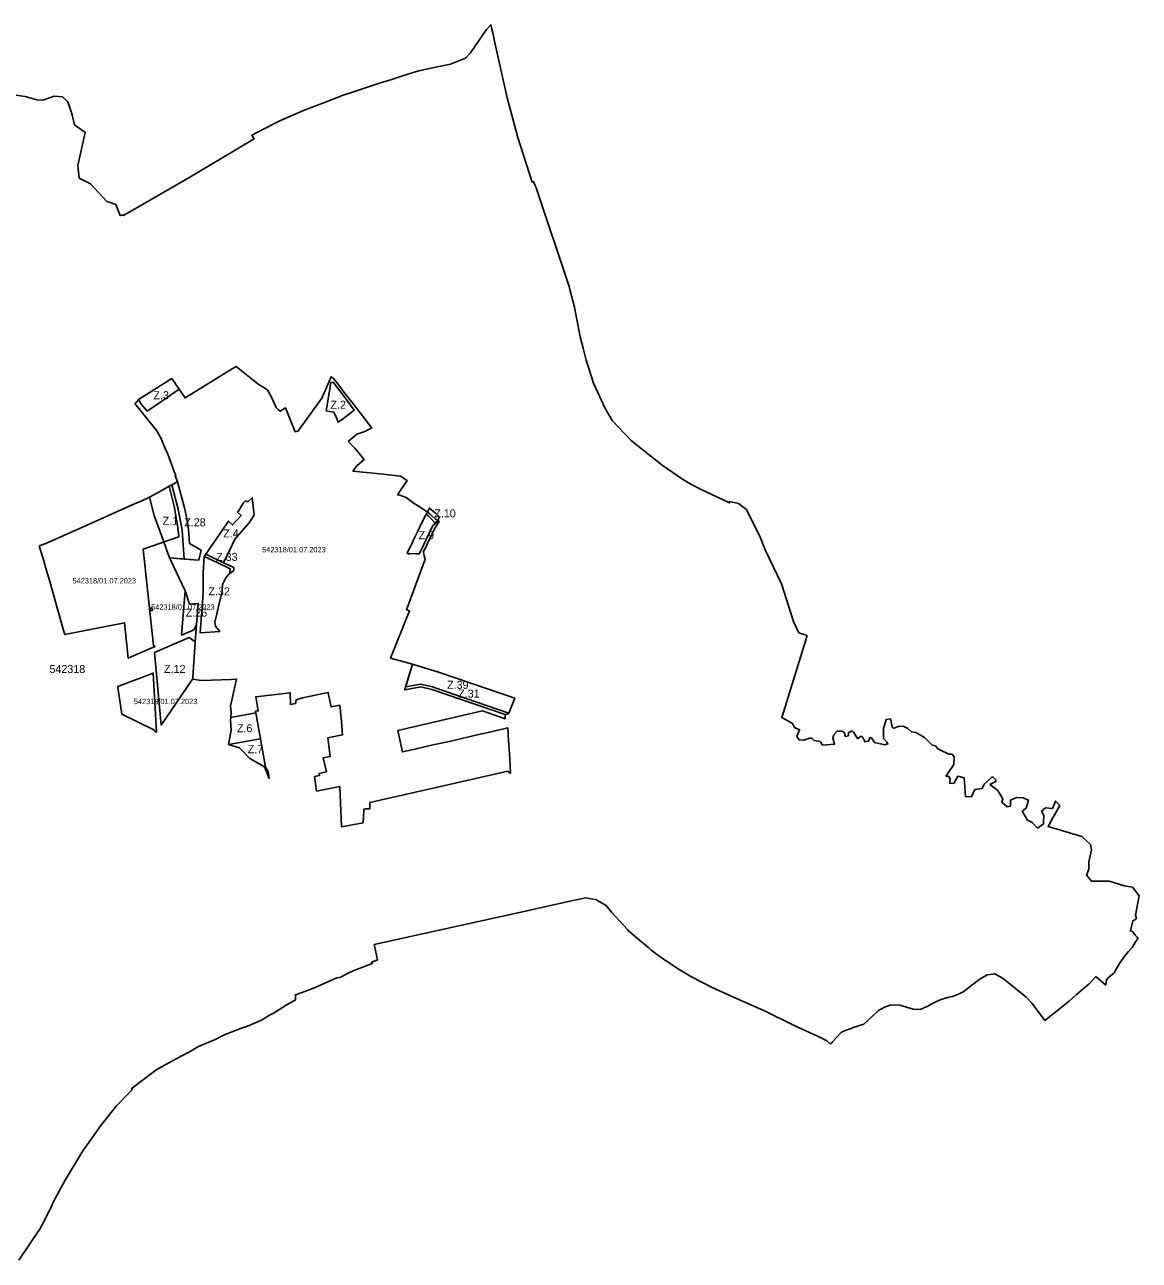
# Model space of a CAD drawing. Extents: x -522079 to -518833, y -1142400 to -1139961.
# Drawn here: x -520921 to -518833, y -1142277 to -1139961 of the extents above; entities that cross this region are included whole.
import ezdxf

# ---------------------------------------------------------------- set-up
doc = ezdxf.new("R2010")
doc.units = 0
for name, color, linetype in [('95410013', 7, 'Continuous'), ('95420023', 7, 'Continuous'), ('95440013', 7, 'Continuous')]:
    doc.layers.add(name, color=color, linetype=linetype)

msp = doc.modelspace()

# ---------------------------------------------------------------- linework, layer by layer
at = {"layer": '95410013'}
for points in [[(-520715.02, -1140671.04), (-520699.13, -1140690.61), (-520673.31, -1140722.41), (-520669.12, -1140730.36), (-520666.3, -1140735.71), (-520657.82, -1140755.57), (-520652.69, -1140766.32), (-520641.11, -1140798.37), (-520638.22, -1140805.93), (-520639.14, -1140806.35), (-520634.79, -1140817.77), (-520621.9, -1140866.86), (-520618.56, -1140880.81), (-520614.37, -1140907.34), (-520612.5, -1140933.48), (-520590.36, -1140946.34), (-520594.75, -1140964.79), (-520649.51, -1140960.76), (-520648.03, -1140963.9), (-520620.51, -1141022.34), (-520612.04, -1141047.58), (-520596.21, -1141046.3), (-520599.33, -1141085.41), (-520601.54, -1141117.64), (-520606.07, -1141183.78), (-520607.02, -1141187.64), (-520589.77, -1141190.43), (-520534.17, -1141188.18), (-520524.27, -1141187.6), (-520535.7, -1141238.47), (-520534.05, -1141249.88), (-520534.84, -1141259.42), (-520488.31, -1141251.1), (-520488.89, -1141247.94), (-520483.58, -1141247.19), (-520488.14, -1141220.84), (-520423.9, -1141213.13), (-520423.33, -1141235.38), (-520413.51, -1141233.43), (-520412.54, -1141226.76), (-520400.61, -1141222.82), (-520352.79, -1141212.63), (-520352.51, -1141213.97), (-520352.46, -1141213.96), (-520347.19, -1141239.81), (-520330.62, -1141236.74), (-520328.39, -1141261.02), (-520327.05, -1141275.53), (-520325.5, -1141292.44), (-520353.1, -1141297.63), (-520348.74, -1141332.58), (-520362.13, -1141335.31), (-520355.94, -1141361.7), (-520369.53, -1141364.42), (-520368.84, -1141368.35), (-520378.01, -1141370.07), (-520374.09, -1141397.41), (-520330.86, -1141389.2), (-520329.77, -1141404.14), (-520327.5, -1141464.71), (-520287.25, -1141456.97), (-520285.53, -1141433.12), (-520285.62, -1141431.18), (-520283.46, -1141431.12), (-520277.92, -1141430.99), (-520274.48, -1141431.01), (-520274.28, -1141419.2), (-520155.8, -1141392.1), (-520016.19, -1141360.33), (-520010.91, -1141364.55), (-520011.78, -1141349.43), (-520013.01, -1141327.96), (-520014.41, -1141303.65), (-520015.8, -1141279.3), (-520055.42, -1141288.36), (-520062.28, -1141289.92), (-520088.69, -1141295.96), (-520120.09, -1141303.14), (-520128.28, -1141304.98), (-520135.15, -1141306.52), (-520161.5, -1141312.42), (-520200.99, -1141321.26), (-520207.86, -1141322.8), (-520213.54, -1141324.07), (-520221.2, -1141287.03), (-520221.83, -1141283.92), (-520063.43, -1141247.22), (-520020.82, -1141261.97), (-520020.92, -1141254.2), (-520158.56, -1141206.98), (-520178.85, -1141202.22), (-520209, -1141207.86), (-520194.38, -1141159.65), (-520235.62, -1141148.58), (-520200.4, -1141059.73), (-520205.51, -1141057.7), (-520170.88, -1140963.13), (-520172.97, -1140956.99), (-520173.77, -1140949.3), (-520154.18, -1140907.23), (-520146.75, -1140896.12), (-520145.76, -1140894.15), (-520144.78, -1140892.2), (-520147.23, -1140890.72), (-520151.38, -1140888.23), (-520158.87, -1140881.01), (-520161.92, -1140878.07), (-520166.62, -1140874.78), (-520176.48, -1140867.88), (-520180.27, -1140865.22), (-520191.59, -1140858.73), (-520196.46, -1140855.08), (-520206.43, -1140847.59), (-520220.12, -1140842.45), (-520222.55, -1140842.43), (-520204.62, -1140815.75), (-520216.9, -1140807.42), (-520249.32, -1140803.75), (-520306.3, -1140797.86), (-520298.77, -1140787.91), (-520285.25, -1140776.21), (-520302.54, -1140754.92), (-520303.74, -1140753.44), (-520314.83, -1140742.62), (-520298.98, -1140728.74), (-520284.03, -1140723.41), (-520276.72, -1140720.19), (-520270.86, -1140717.61), (-520287.89, -1140694.59), (-520300.9, -1140678.05), (-520307.57, -1140669.43), (-520324.2, -1140648.06), (-520334.5, -1140634.63), (-520342.44, -1140624.55), (-520346.89, -1140621.24), (-520364.42, -1140661.36), (-520399.89, -1140710.42), (-520399.9, -1140710.42), (-520405.96, -1140718.81), (-520407.37, -1140721.08), (-520408.23, -1140722.45), (-520414.39, -1140724.32), (-520422.23, -1140704.1), (-520432.59, -1140679.54), (-520442.27, -1140685.74), (-520445.91, -1140682.53), (-520449.96, -1140678.96), (-520457.96, -1140660.67), (-520465.4, -1140646.75), (-520470.21, -1140643.01), (-520481.74, -1140636.06), (-520493.55, -1140626.8), (-520525.02, -1140602.15), (-520527.15, -1140603.46), (-520617.05, -1140658.61), (-520620.66, -1140660.83), (-520631.48, -1140644.23), (-520662.52, -1140665.44), (-520691.74, -1140685.4), (-520702.26, -1140672.84), (-520707.94, -1140663.79), (-520710.41, -1140667.24)], [(-520893.74, -1140937.98), (-520888.93, -1140954.41), (-520885.58, -1140965.84), (-520881.52, -1140979.72), (-520872.93, -1141009.05), (-520861.45, -1141049.84), (-520847.24, -1141100.33), (-520846.14, -1141104.23), (-520733.88, -1141082.24), (-520727.16, -1141148.38), (-520686.99, -1141131.09), (-520676.95, -1141126.77), (-520679.92, -1141124.76), (-520682.4, -1141101.39), (-520695.94, -1140973.65), (-520699.09, -1140943.92), (-520632.04, -1140920.85), (-520634.37, -1140902.81), (-520641.23, -1140863.72), (-520646.19, -1140843.58), (-520650.7, -1140826.31), (-520665.74, -1140834.79), (-520687.49, -1140846.81), (-520701.37, -1140853.35), (-520715.12, -1140859.45), (-520801.45, -1140897.78), (-520881.74, -1140933.43)], [(-520681.75, -1141059.18), (-520682.32, -1141054.61), (-520685.9, -1141055.06), (-520685.33, -1141059.63)], [(-520674.18, -1141286.49), (-520680.34, -1141176.38), (-520746.65, -1141201.66), (-520746.38, -1141203.48), (-520739.03, -1141253.62), (-520679.28, -1141282.96), (-520675.31, -1141287.41)]]:
    msp.add_lwpolyline(points, close=True, dxfattribs=at)
at = {"layer": '95420023'}
for points in [[(-520631.48, -1140644.23), (-520645.69, -1140624.14), (-520707.94, -1140663.79), (-520702.26, -1140672.84), (-520691.74, -1140685.4), (-520662.52, -1140665.44)], [(-520351.39, -1140655.57), (-520356.53, -1140684.75), (-520353.6, -1140685.32), (-520345.87, -1140686.81), (-520341.7, -1140687.61), (-520339.66, -1140692.44), (-520335.84, -1140701.48), (-520334.3, -1140706.02), (-520326.31, -1140701.14), (-520303.56, -1140683.6), (-520324.4, -1140655.71), (-520343.28, -1140631.04), (-520347.36, -1140631.75)], [(-520687.49, -1140846.81), (-520678.48, -1140881.15), (-520660.47, -1140930.63), (-520649.51, -1140960.76), (-520622.44, -1140962.75), (-520626.29, -1140908.87), (-520633.62, -1140869.48), (-520645.66, -1140823.61), (-520650.7, -1140826.31), (-520665.74, -1140834.79)], [(-520622.44, -1140962.75), (-520594.75, -1140964.79), (-520590.36, -1140946.34), (-520612.5, -1140933.48), (-520614.37, -1140907.34), (-520618.56, -1140880.81), (-520621.9, -1140866.86), (-520634.79, -1140817.77), (-520645.66, -1140823.61), (-520633.62, -1140869.48), (-520626.29, -1140908.87)], [(-520197.39, -1140937.44), (-520204.29, -1140951.99), (-520201.3, -1140953.32), (-520201.27, -1140953.32), (-520200.79, -1140952.24), (-520189.01, -1140952.86), (-520181.77, -1140953.24), (-520180.26, -1140950.09), (-520156.19, -1140899.86), (-520151.68, -1140896.26), (-520164.55, -1140881.96), (-520168.95, -1140879.03), (-520170.08, -1140881.1), (-520178.74, -1140898.05), (-520184.7, -1140910.65), (-520191.17, -1140924.29), (-520193, -1140928.16), (-520196.08, -1140934.67)], [(-520168.95, -1140879.03), (-520164.55, -1140881.96), (-520151.68, -1140896.26), (-520149.94, -1140892.73), (-520148.74, -1140894), (-520148.27, -1140892.97), (-520147.23, -1140890.72), (-520143.83, -1140883.35), (-520152.09, -1140876.15), (-520162.5, -1140867.24), (-520166.62, -1140874.78), (-520167.79, -1140876.9)], [(-520536.52, -1140989.65), (-520536.41, -1140980.8), (-520560.76, -1140969.3), (-520584.75, -1140957.97), (-520586.68, -1140988.64), (-520586.76, -1141021.16), (-520586.99, -1141025.98), (-520587.85, -1141044.25), (-520588.29, -1141049.68), (-520590.32, -1141074.97), (-520592.43, -1141100.83), (-520555.74, -1141098.46), (-520563.4, -1141088.78), (-520565.18, -1141081.15), (-520561.24, -1141065.24), (-520556.5, -1141046.1), (-520551.07, -1141024.16), (-520550.66, -1141010.15), (-520545.15, -1140999.12), (-520540.36, -1140992.71)], [(-520596.21, -1141046.3), (-520612.04, -1141047.58), (-520620.51, -1141022.34), (-520627.13, -1141105.32), (-520605.48, -1141096), (-520603.47, -1141094.45), (-520599.33, -1141085.41)], [(-520601.54, -1141117.64), (-520612.8, -1141110.04), (-520677.78, -1141138.02), (-520665.65, -1141273.94), (-520607.02, -1141187.64), (-520606.07, -1141183.78)], [(-520194.38, -1141159.65), (-520207.36, -1141202.47), (-520178.73, -1141197.11), (-520176.64, -1141197.6), (-520157.17, -1141202.17), (-520156.44, -1141202.42), (-520153.86, -1141203.31), (-520013.82, -1141251.35), (-520002.99, -1141223.35), (-520143.75, -1141175.06)], [(-520209, -1141207.86), (-520178.85, -1141202.22), (-520158.56, -1141206.98), (-520020.92, -1141254.2), (-520014.17, -1141252.24), (-520013.82, -1141251.35), (-520153.86, -1141203.31), (-520156.44, -1141202.42), (-520157.17, -1141202.17), (-520176.64, -1141197.6), (-520178.73, -1141197.11), (-520207.36, -1141202.47)], [(-520488.31, -1141251.1), (-520534.84, -1141259.42), (-520535.3, -1141264.93), (-520534.35, -1141283.17), (-520539.2, -1141310.09), (-520479.49, -1141299.41)], [(-520479.49, -1141299.41), (-520539.2, -1141310.09), (-520518.61, -1141316.36), (-520499.06, -1141336.21), (-520471.76, -1141351.9), (-520463.1, -1141373.93), (-520465.21, -1141361), (-520469.72, -1141352.88)]]:
    msp.add_lwpolyline(points, close=True, dxfattribs=at)
for points in [[(-520514.41, -1140910.27), (-520500.98, -1140895.73), (-520497.04, -1140889.19), (-520491.41, -1140879.85), (-520492.53, -1140869.55), (-520494.89, -1140847.8), (-520502.85, -1140855.53), (-520507.49, -1140853.67), (-520511.48, -1140857.9), (-520516.84, -1140866.53), (-520521.46, -1140873.68)], [(-520515.64, -1140881.37), (-520531.52, -1140898.7), (-520538.57, -1140892.18), (-520539.31, -1140891.51), (-520549.95, -1140907.16), (-520562.58, -1140925.73), (-520581.88, -1140953.8), (-520548.43, -1140969.6), (-520536.98, -1140945.57), (-520527.38, -1140925.42), (-520514.41, -1140910.27)], [(-520521.46, -1140873.68), (-520522.62, -1140874.92)], [(-520522.62, -1140874.92), (-520515.64, -1140881.37)], [(-520581.88, -1140953.8), (-520584.75, -1140957.97), (-520560.76, -1140969.3), (-520536.41, -1140980.8), (-520536.52, -1140989.65), (-520529.52, -1140984.06), (-520529.45, -1140978.56), (-520536.34, -1140975.31), (-520548.43, -1140969.6), (-520581.88, -1140953.8)]]:
    msp.add_lwpolyline(points, dxfattribs=at)
at = {"layer": '95440013'}
msp.add_lwpolyline([(-520941.45, -1140093.01), (-520920.41, -1140096.1), (-520898.59, -1140102.13), (-520887.39, -1140102.82), (-520865.88, -1140095.27), (-520850.56, -1140096.88), (-520840.13, -1140106.03), (-520833.95, -1140124.09), (-520832.38, -1140130.38), (-520827.76, -1140148.83), (-520807.65, -1140163.22), (-520821.47, -1140225.09), (-520818.83, -1140248.97), (-520797.63, -1140259.52), (-520767.33, -1140292.73), (-520763.01, -1140294.16), (-520750.13, -1140298.42), (-520742.16, -1140319.24), (-520738.8, -1140318.04), (-520737.2, -1140317.47), (-520736.37, -1140319.22), (-520728.21, -1140314.51), (-520611.62, -1140247.2), (-520491.09, -1140175.17), (-520495.34, -1140168.3), (-520483.64, -1140162.33), (-520442, -1140141.08), (-520418.53, -1140130.92), (-520398.93, -1140122.43), (-520359.48, -1140107), (-520324.32, -1140093.25), (-520303.34, -1140086.47), (-520288.09, -1140081.53), (-520260.01, -1140072.45), (-520246.26, -1140068.01), (-520233.47, -1140063.87), (-520226.58, -1140061.71), (-520194.98, -1140051.81), (-520182.69, -1140047.96), (-520145.26, -1140039.86), (-520123.02, -1140035.05), (-520094.95, -1140023.82), (-520085.97, -1140013.91), (-520055.62, -1139970.09), (-520047.76, -1139961.42), (-520045.81, -1139969.91), (-520044.21, -1139976.9), (-520040.68, -1139992.3), (-520017.23, -1140098.3), (-519997.42, -1140172.65), (-519970.54, -1140256.24), (-519967.99, -1140255.12), (-519967.34, -1140256.59), (-519967.14, -1140257.04), (-519965.23, -1140261.32), (-519965.02, -1140261.78), (-519963.47, -1140265.25), (-519901.13, -1140452.27), (-519899.47, -1140457.37), (-519890.68, -1140491.02), (-519880.22, -1140546.4), (-519874.89, -1140567.55), (-519868.98, -1140589.75), (-519867.83, -1140594.09), (-519855.18, -1140633.03), (-519833.7, -1140680.7), (-519820.17, -1140703.4), (-519783.91, -1140740.96), (-519726.89, -1140786.75), (-519688.67, -1140812.79), (-519674.4, -1140821.79), (-519656.36, -1140831.22), (-519600.86, -1140857.49), (-519600.42, -1140854.95), (-519583.72, -1140858.5), (-519575.54, -1140864.6), (-519569.14, -1140869.38), (-519544.31, -1140918.54), (-519533.66, -1140945.39), (-519503.31, -1141009.21), (-519480.71, -1141079.48), (-519470.66, -1141100.87), (-519455.06, -1141106.14), (-519456.05, -1141109.33), (-519457.77, -1141114.91), (-519459.37, -1141120.07), (-519501.33, -1141255.67), (-519501.64, -1141256.67), (-519502.46, -1141259.44), (-519482.78, -1141270.88), (-519478.58, -1141278.28), (-519469.18, -1141282.65), (-519474.2, -1141295.1), (-519470.14, -1141301.74), (-519461.74, -1141302), (-519449.98, -1141298.09), (-519446.22, -1141298.48), (-519441.7, -1141302.87), (-519430.99, -1141304.77), (-519426.16, -1141311.48), (-519403.83, -1141309.49), (-519406.68, -1141297.5), (-519405.2, -1141292.02), (-519399.13, -1141285.07), (-519389.78, -1141285.13), (-519385.69, -1141287.55), (-519385.12, -1141289.38), (-519383.31, -1141295.11), (-519377.88, -1141293.85), (-519377.66, -1141291.53), (-519377.33, -1141288.06), (-519373.33, -1141286.11), (-519370.55, -1141284.76), (-519368.04, -1141287.17), (-519367.51, -1141288.01), (-519361.74, -1141297.24), (-519360.6, -1141299.07), (-519359.18, -1141298.18), (-519353.95, -1141294.93), (-519351.06, -1141296.96), (-519347.55, -1141303.63), (-519346.7, -1141305.23), (-519340.12, -1141304.19), (-519339.07, -1141301.4), (-519337.51, -1141297.26), (-519333.7, -1141298.67), (-519329.18, -1141306.68), (-519309.3, -1141311.02), (-519303.86, -1141309.05), (-519304.74, -1141307.68), (-519305.93, -1141305.82), (-519312.28, -1141299.01), (-519311.83, -1141280.54), (-519306.82, -1141263.47), (-519299.19, -1141262.23), (-519295.1, -1141279.15), (-519292.59, -1141279.53), (-519282.24, -1141275.71), (-519273.89, -1141276.5), (-519266.36, -1141280.43), (-519259.58, -1141286.33), (-519251.16, -1141288.07), (-519234.97, -1141297.23), (-519220.59, -1141311.22), (-519214.82, -1141312.52), (-519210.53, -1141318.6), (-519206.65, -1141320.44), (-519189.49, -1141328.56), (-519183.26, -1141328.59), (-519179.55, -1141333.52), (-519180.48, -1141347.87), (-519192.3, -1141365.49), (-519194.96, -1141369.43), (-519190.42, -1141369.81), (-519187.2, -1141374.82), (-519188.01, -1141382.78), (-519180.54, -1141383.29), (-519172.49, -1141369.75), (-519161.16, -1141372.68), (-519158.19, -1141407.51), (-519147.23, -1141408.12), (-519140.85, -1141394.82), (-519127.25, -1141392.73), (-519123.4, -1141384.39), (-519109.18, -1141371.2), (-519106.36, -1141371.37), (-519101.55, -1141376.47), (-519101.7, -1141379.43), (-519112.59, -1141385.36), (-519098.12, -1141396.65), (-519088.18, -1141412.32), (-519090.32, -1141418.48), (-519080.26, -1141427.02), (-519074.35, -1141425.83), (-519073.85, -1141414.66), (-519062.78, -1141409.81), (-519050.33, -1141409.98), (-519040.39, -1141414.74), (-519044.82, -1141429.69), (-519052, -1141435.32), (-519042.3, -1141452.19), (-519033.46, -1141456.53), (-519023.29, -1141466.86), (-519012.53, -1141459.04), (-519012.34, -1141454.52), (-519011.87, -1141443.33), (-519015.74, -1141435.38), (-519008.63, -1141428.83), (-518995.53, -1141430.25), (-518989.97, -1141416.33), (-518981.74, -1141424.63), (-518994.55, -1141447.83), (-519001.41, -1141460.26), (-519003.59, -1141464.2), (-518940.71, -1141482.48), (-518924.49, -1141497.8), (-518922.06, -1141507.35), (-518927.02, -1141530.23), (-518927.11, -1141543.74), (-518931.43, -1141555), (-518922.51, -1141566.63), (-518889.18, -1141566.18), (-518860.53, -1141575.36), (-518845.76, -1141577.71), (-518832.78, -1141593.74), (-518840.17, -1141630.23), (-518837.74, -1141636.08), (-518840.9, -1141638.87), (-518844.96, -1141640.98), (-518849.41, -1141659.71), (-518844.75, -1141661.05), (-518840.16, -1141667.91), (-518837.05, -1141671.02), (-518835.83, -1141672.48), (-518835.18, -1141672.79), (-518835.69, -1141673.66), (-518840.27, -1141681.38), (-518845.39, -1141690.02), (-518852.72, -1141698.29), (-518859.88, -1141706.38), (-518869.99, -1141720.5), (-518876.08, -1141731.29), (-518880.1, -1141738.42), (-518889.83, -1141746.28), (-518894.38, -1141751.49), (-518895.73, -1141761.19), (-518914.26, -1141745.22), (-518926.6, -1141758.63), (-518950.14, -1141779.05), (-518963.91, -1141791), (-518994.87, -1141815.89), (-518997.83, -1141818.27), (-519007.06, -1141825.69), (-519009.58, -1141827.71), (-519033.21, -1141795.69), (-519044.72, -1141783.93), (-519087.6, -1141748.94), (-519103.5, -1141739.96), (-519106.29, -1141740.33), (-519117.64, -1141741.85), (-519132.98, -1141750.7), (-519141.38, -1141757.45), (-519162.82, -1141773.79), (-519171.52, -1141778.29), (-519182.83, -1141782.69), (-519192.31, -1141784.44), (-519205.85, -1141788.49), (-519209.88, -1141790.38), (-519220.64, -1141795.43), (-519228.74, -1141800.67), (-519243.51, -1141806.68), (-519256.37, -1141806.05), (-519281.47, -1141798.57), (-519297.93, -1141798.04), (-519308.25, -1141801.56), (-519310.14, -1141802.21), (-519316.53, -1141805.97), (-519321.4, -1141808.82), (-519348.63, -1141834.32), (-519368.78, -1141840.86), (-519372.86, -1141842.19), (-519376.08, -1141843.54), (-519377.1, -1141843.96), (-519389.29, -1141849.01), (-519391.5, -1141849.93), (-519408.1, -1141868.36), (-519409.46, -1141869.87), (-519411.05, -1141871.62), (-519418.41, -1141865.69), (-519428.71, -1141859.77), (-519471.59, -1141840.28), (-519480.84, -1141836.08), (-519533.59, -1141810.27), (-519593.13, -1141783.65), (-519633.06, -1141765.56), (-519673.22, -1141744.78), (-519694.8, -1141731.79), (-519718.63, -1141715.98), (-519733.23, -1141706.57), (-519747.91, -1141694.83), (-519751.14, -1141692.22), (-519776.39, -1141670.73), (-519790.37, -1141658.77), (-519791.74, -1141656.89), (-519821.3, -1141625.26), (-519831.88, -1141612.23), (-519847.75, -1141602.33), (-519849.83, -1141601.06), (-519870.13, -1141597.7), (-519887.54, -1141601.15), (-519894.12, -1141602.61), (-519988.36, -1141623.57), (-520003.05, -1141627.05), (-520133.25, -1141655.87), (-520266.08, -1141685.14), (-520265.6, -1141687.35), (-520259.91, -1141713.53), (-520270.75, -1141718.04), (-520269.8, -1141720.57), (-520302.33, -1141733.12), (-520311.37, -1141736.89), (-520330.69, -1141747.06), (-520336.12, -1141747.68), (-520379.93, -1141766.64), (-520396.49, -1141772.96), (-520413.8, -1141779.11), (-520413.91, -1141788.74), (-520421.03, -1141792.82), (-520431, -1141798.52), (-520443.29, -1141806.35), (-520453.46, -1141812.83), (-520454.47, -1141813.35), (-520454.91, -1141813.57), (-520458.87, -1141815.72), (-520465.55, -1141819.35), (-520477.66, -1141826.82), (-520503.7, -1141838.29), (-520515.18, -1141841.56), (-520545.58, -1141853.73), (-520565.76, -1141863.93), (-520595.23, -1141876.48), (-520613.84, -1141887.11), (-520637.23, -1141899.54), (-520669.31, -1141916.94), (-520675.72, -1141920.42), (-520721.33, -1141955.66), (-520719.53, -1141957.2), (-520728.5, -1141965.87), (-520748.85, -1141987.64), (-520778.35, -1142023.99), (-520792.36, -1142043.35), (-520798.04, -1142051.82), (-520812.28, -1142071.49), (-520845.48, -1142126.69), (-520864.2, -1142161.29), (-520868.95, -1142171.08), (-520869.86, -1142172.95), (-520871.84, -1142177.03), (-520872.25, -1142177.87), (-520882.99, -1142199.96), (-520892.25, -1142217.33), (-520932.3, -1142276.81)], dxfattribs=at)

# ---------------------------------------------------------------- texts
at = {"layer": '95410013'}
for rotation, p in [(360, (-520476.21, -1140950.19)), (360, (-520831.51, -1141008.42)), (0, (-520684.26, -1141057.68)), (360, (-520716.65, -1141234.64))]:
    msp.add_text('542318/01.07.2023', height=10, rotation=rotation, dxfattribs=at).set_placement(p)
at = {"layer": '95420023'}
for s, rotation, p in [('Z.3', 360, (-520679.91, -1140663.19)), ('Z.2', 0, (-520348.21, -1140681.03)), ('Z.1', 0, (-520662.57, -1140898.49)), ('Z.10', 0, (-520153.64, -1140884.56)), ('Z.28', 0, (-520622.14, -1140901.45)), ('Z.4', 360, (-520549.16, -1140922.26)), ('Z.9', 360, (-520183.15, -1140925.54)), ('Z.33', 0, (-520562.41, -1140966.17)), ('Z.32', 0, (-520576.87, -1141030.8)), ('Z.26', 360, (-520619.41, -1141070.71)), ('Z.12', 0, (-520659.95, -1141176.13)), ('Z.39', 0, (-520129.7, -1141205.94)), ('Z.31', 0, (-520108.93, -1141222.39)), ('Z.6', 0, (-520523.5, -1141287.35)), ('Z.7', 360, (-520503.29, -1141326.57))]:
    msp.add_text(s, height=15, rotation=rotation, dxfattribs=at).set_placement(p)
at = {"layer": '95440013'}
msp.add_text('542318', height=15, rotation=360, dxfattribs=at).set_placement((-520874.72, -1141176.29))

doc.saveas('drawing.dxf')
